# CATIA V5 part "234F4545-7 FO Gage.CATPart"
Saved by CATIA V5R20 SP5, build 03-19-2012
Part number: 234F4545-7 FO Gage
Bounding box of the stored display mesh (mm): x 31605.646 to 31929.283, y -11323.263 to -11195.946, z 5422.049 to 5471.491
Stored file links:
  C:\Users\rem1927\Desktop\Current Explicit Composite Demo\234F4545-7 FO Gage.CATPart
  C:\Users\rem1927\Desktop\Current Explicit Composite Demo\234B5678-1 Composite Product.CATProduct
  C:\Users\rem1927\Desktop\Tess Product Demo R20\234B5678_2_Rev_.CATPart
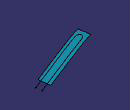
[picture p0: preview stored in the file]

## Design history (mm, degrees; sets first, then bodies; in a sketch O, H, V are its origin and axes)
Set1 "Const"
  Plane1: type Offset, RefPlane Plane9, Offset 11.43
  Plane2: type Offset, RefPlane Plane1, Offset 25.4
  Plane3: type Offset, RefPlane Plane10, Offset 203.2
  Split1: ToCut DatumSurface1, Cutting Plane3
  Plane4: stored without definition
  Intersect1: ToIntersect1 Plane1, ToIntersect2 Split1
  Intersect2: ToIntersect1 Plane2, ToIntersect2 Split1
  Split2: ToCut Intersect2, Cutting Plane4
  Split3: ToCut Intersect1, Cutting Plane4
  Curve1: Elements (vertex of Split3; vertex of Split2), Support Split1
  Join1: Elements (Split3; Curve1; Split2)
  Sweep1: type Circle, Guide Join1, Radius 0.0635
  Plane5: type Normal, Curve Join1, RefPoint vertex of Intersect1
  Plane6: type Offset, RefPlane Plane5, Offset 3.81
  Split4: ToCut Intersect1, Cutting Plane6
  Sweep2: type Circle, Guide Split4, Radius 1.27
  Plane7: type Normal, Curve Intersect2, RefPoint vertex of Intersect2
  Plane8: type Offset, RefPlane Plane7, Offset 3.81
  Split5: ToCut Intersect2, Cutting Plane8
  Sweep3: type Circle, Guide Split5, Radius 1.27
Set2 "Adheasive Layer"
  Extract1 "Base": ExtractElem face of DatumSurface1
  Split6 "EOP Trim": ToCut Extract1, Cutting (DatumSurface2; DatumSurface3; Plane9)
  Extract2 "Adheasive": ExtractElem face of ThickSurface1
Set3
  Plane9 "EOP Flange": linked copy from another document
  Plane10 "reference_plane": linked copy from another document
  DatumSurface1 "Core Layup Surface": linked copy from another document
  DatumSurface2 "aft_trim_surface": linked copy from another document
  DatumSurface3 "fwd_trim_surface": linked copy from another document
Body1 "Const Solid for adheasive"
  ThickSurface1: BotOffset 0, Surface Split6, TopOffset 2.54
  Fillet1: radius 6.35, on edge [face of ThickSurface1 | face of ThickSurface1] (x2)
Body2 "FO Cable" (main body)
  CloseSurface1: CloseElement Sweep1
  Body3 "Connector 1"
    CloseSurface2: CloseElement Sweep2
  Add1: tool Body3
  Body4 "Connector 2"
    CloseSurface3: CloseElement Sweep3
  Add2: tool Body4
